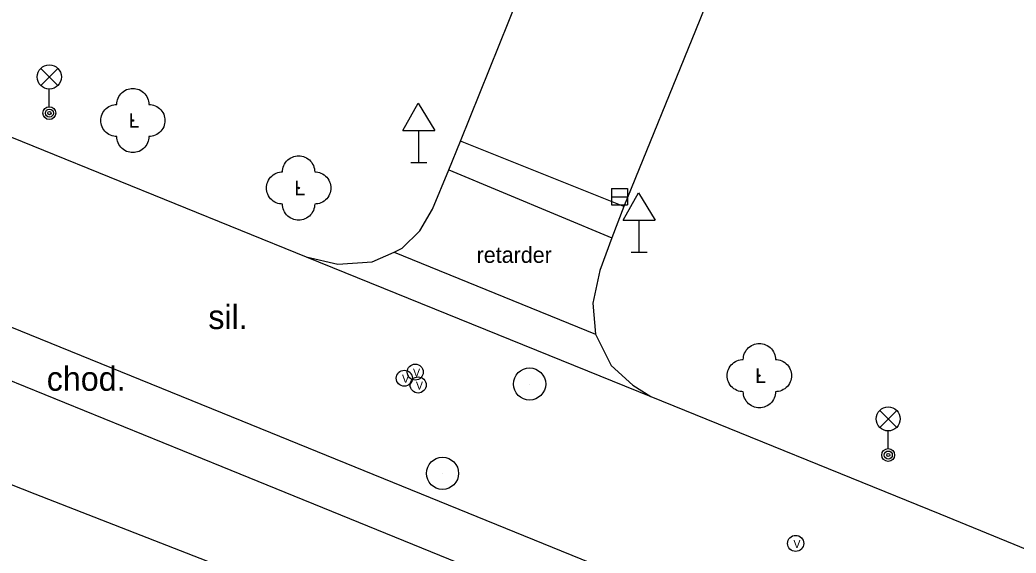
# Model space of a CAD drawing. Extents: x -836568 to -836015, y -1070547 to -1070212.
# Drawn here: x -836360.58 to -836329.58, y -1070416.28 to -1070399.69 of the extents above; entities that cross this region are included whole.
import ezdxf

# ---------------------------------------------------------------- set-up
doc = ezdxf.new("R2010")
doc.units = 0
for name, color, linetype in [('BodPole_mer', 7, 'Continuous'), ('Doprava_body', 7, 'Continuous'), ('Doprava_hranice', 7, 'Continuous'), ('Doprava_kody', 7, 'Continuous'), ('Doprava_popis', 7, 'Continuous'), ('PovrZnIS_body', 7, 'Continuous'), ('Zelen_body', 7, 'Continuous')]:
    doc.layers.add(name, color=color, linetype=linetype)

msp = doc.modelspace()

# ---------------------------------------------------------------- linework, layer by layer
at = {"layer": 'BodPole_mer'}
for p, q in [((-836339.56, -1070400.02), (-836339.56, -1070400.02)), ((-836359.67, -1070402.59), (-836359.67, -1070402.59)), ((-836357.07, -1070402.82), (-836357.07, -1070402.82)), ((-836346.87, -1070403.46), (-836346.87, -1070403.46)), ((-836348.17, -1070404.13), (-836348.17, -1070404.13)), ((-836347.24, -1070404.36), (-836347.24, -1070404.36)), ((-836351.91, -1070404.92), (-836351.91, -1070404.92)), ((-836341.92, -1070405.19), (-836341.92, -1070405.19)), ((-836347.74, -1070405.58), (-836347.74, -1070405.58)), ((-836341.79, -1070405.5), (-836341.79, -1070405.5)), ((-836348.14, -1070406.25), (-836348.14, -1070406.25)), ((-836342.16, -1070406.47), (-836342.16, -1070406.47)), ((-836348.69, -1070406.79), (-836348.69, -1070406.79)), ((-836351.68, -1070407.06), (-836351.68, -1070407.06)), ((-836348.94, -1070406.92), (-836348.94, -1070406.92)), ((-836341.31, -1070406.92), (-836341.31, -1070406.92)), ((-836350.69, -1070407.29), (-836350.69, -1070407.29)), ((-836349.62, -1070407.22), (-836349.62, -1070407.22)), ((-836342.54, -1070407.49), (-836342.54, -1070407.49)), ((-836342.75, -1070408.5), (-836342.75, -1070408.5)), ((-836342.67, -1070409.47), (-836342.67, -1070409.47)), ((-836342.18, -1070410.44), (-836342.18, -1070410.44)), ((-836348.62, -1070410.84), (-836348.62, -1070410.84)), ((-836348.28, -1070410.65), (-836348.28, -1070410.65)), ((-836337.57, -1070410.76), (-836337.57, -1070410.76)), ((-836348.19, -1070411.05), (-836348.19, -1070411.05)), ((-836344.72, -1070411.02), (-836344.72, -1070411.02)), ((-836341.51, -1070411.06), (-836341.51, -1070411.06)), ((-836340.95, -1070411.41), (-836340.95, -1070411.41)), ((-836353.67, -1070412.18), (-836353.67, -1070412.18)), ((-836333.56, -1070413.23), (-836333.56, -1070413.23)), ((-836354.29, -1070413.6), (-836354.29, -1070413.6)), ((-836347.43, -1070413.8), (-836347.43, -1070413.8)), ((-836360.12, -1070414.44), (-836360.12, -1070414.44)), ((-836331.95, -1070415.06), (-836331.95, -1070415.06)), ((-836336.44, -1070415.98), (-836336.44, -1070415.98))]:
    msp.add_line(p, q, dxfattribs=at)
at = {"layer": 'Doprava_body'}
for p, q in [((-836348.67, -1070403.13), (-836348.189, -1070402.276)), ((-836348.189, -1070402.276), (-836347.67, -1070403.13)), ((-836348.67, -1070403.13), (-836347.67, -1070403.13)), ((-836348.17, -1070404.13), (-836348.17, -1070403.13)), ((-836348.42, -1070404.13), (-836347.92, -1070404.13)), ((-836341.81, -1070405.92), (-836341.329, -1070405.066)), ((-836341.329, -1070405.066), (-836340.81, -1070405.92)), ((-836341.81, -1070405.92), (-836340.81, -1070405.92)), ((-836341.31, -1070406.92), (-836341.31, -1070405.92)), ((-836341.56, -1070406.92), (-836341.06, -1070406.92))]:
    msp.add_line(p, q, dxfattribs=at)
at = {"layer": 'Doprava_hranice'}
for p, q in [((-836341.79, -1070405.5), (-836346.87, -1070403.46)), ((-836347.24, -1070404.36), (-836342.16, -1070406.47)), ((-836348.94, -1070406.92), (-836342.67, -1070409.47))]:
    msp.add_line(p, q, dxfattribs=at)
for points in [[(-836331.66, -1070380.54), (-836339.56, -1070400.02), (-836341.79, -1070405.5), (-836342.16, -1070406.47), (-836342.54, -1070407.49), (-836342.75, -1070408.5), (-836342.67, -1070409.47), (-836342.18, -1070410.44), (-836341.51, -1070411.06), (-836340.95, -1070411.41)], [(-836354.29, -1070413.6), (-836369.6, -1070407.37), (-836381.91, -1070402.37), (-836385.59, -1070400.85), (-836388.36, -1070399.67), (-836391.13, -1070398.46), (-836393.85, -1070397.22), (-836395.73, -1070396.35), (-836398.41, -1070395.08), (-836401.16, -1070393.77), (-836403.85, -1070392.4), (-836406.54, -1070391.05), (-836409.24, -1070389.65), (-836411.89, -1070388.24), (-836414.55, -1070386.78), (-836417.54, -1070385.1), (-836418.59, -1070387.07)], [(-836396.93, -1070387.99), (-836395.12, -1070388.87), (-836392.38, -1070390.14), (-836389.65, -1070391.39), (-836386.89, -1070392.61), (-836384.17, -1070393.78), (-836382.29, -1070394.58), (-836379.84, -1070395.6), (-836379.24, -1070395.86), (-836376.76, -1070396.89), (-836369.55, -1070399.81), (-836361.91, -1070402.91), (-836351.68, -1070407.06)], [(-836294.78, -1070436.14), (-836298.75, -1070434.54), (-836300.99, -1070433.61), (-836301.95, -1070433.21), (-836302.68, -1070432.9), (-836308.94, -1070430.38), (-836313.57, -1070428.51), (-836318.21, -1070426.63), (-836324.7, -1070423.98), (-836329.32, -1070422.08), (-836333.96, -1070420.19), (-836342.84, -1070416.58), (-836353.67, -1070412.18), (-836369.06, -1070405.92), (-836381.28, -1070400.95), (-836385.01, -1070399.41), (-836387.75, -1070398.25), (-836390.49, -1070397.04), (-836393.21, -1070395.81), (-836395.03, -1070394.97), (-836397.75, -1070393.68), (-836399.24, -1070392.97)], [(-836351.68, -1070407.06), (-836350.69, -1070407.29), (-836349.62, -1070407.22), (-836348.94, -1070406.92), (-836348.69, -1070406.79), (-836348.14, -1070406.25), (-836347.74, -1070405.58), (-836347.24, -1070404.36), (-836346.87, -1070403.46), (-836345.07, -1070398.97)], [(-836351.68, -1070407.06), (-836340.95, -1070411.41), (-836331.95, -1070415.06), (-836322.39, -1070418.98), (-836311.25, -1070423.49), (-836299.94, -1070428.08), (-836299, -1070428.44), (-836298.27, -1070428.74)], [(-836370.7, -1070410.27), (-836360.12, -1070414.44), (-836352.3, -1070417.49), (-836345.8, -1070420.64)], [(-836282.83, -1070440.54), (-836283.39, -1070441.99), (-836288.97, -1070439.98), (-836292.82, -1070438.51), (-836295.89, -1070437.33), (-836299.06, -1070436.06), (-836309.56, -1070431.79), (-836314.22, -1070429.91), (-836319.37, -1070427.82), (-836325.29, -1070425.39), (-836329.9, -1070423.52), (-836331.04, -1070426.22), (-836335.67, -1070424.36), (-836334.55, -1070421.64), (-836343.54, -1070417.97), (-836354.29, -1070413.6)]]:
    msp.add_lwpolyline(points, dxfattribs=at)
at = {"layer": 'PovrZnIS_body'}
for p, q in [((-836359.935, -1070401.73), (-836359.405, -1070401.2)), ((-836359.935, -1070401.2), (-836359.405, -1070401.73)), ((-836359.67, -1070402.39), (-836359.67, -1070401.84)), ((-836342.17, -1070404.94), (-836341.67, -1070404.94)), ((-836342.17, -1070404.94), (-836342.17, -1070405.44)), ((-836341.67, -1070404.94), (-836341.67, -1070405.44)), ((-836342.17, -1070405.19), (-836341.67, -1070405.19)), ((-836342.17, -1070405.44), (-836341.67, -1070405.44)), ((-836333.825, -1070412.37), (-836333.295, -1070411.84)), ((-836333.825, -1070411.84), (-836333.295, -1070412.37)), ((-836333.56, -1070413.03), (-836333.56, -1070412.48))]:
    msp.add_line(p, q, dxfattribs=at)
for centre, radius in [((-836348.28, -1070410.65), 0.25), ((-836344.72, -1070411.02), 0.5), ((-836348.62, -1070410.84), 0.25), ((-836348.19, -1070411.05), 0.25), ((-836347.43, -1070413.8), 0.5), ((-836336.44, -1070415.98), 0.25)]:
    msp.add_circle(centre, radius, dxfattribs=at)
for centre, major_axis in [((-836359.67, -1070401.465), (0.375, 0)), ((-836359.67, -1070402.59), (0.2, 0)), ((-836359.666, -1070402.59), (0.125, 0)), ((-836359.666, -1070402.59), (0.05, 0)), ((-836333.56, -1070412.105), (0.375, 0)), ((-836333.56, -1070413.23), (0.2, 0)), ((-836333.556, -1070413.23), (0.125, 0)), ((-836333.556, -1070413.23), (0.05, 0))]:
    msp.add_ellipse(centre, major_axis=major_axis, ratio=0.999998, dxfattribs=at)
at = {"layer": 'Zelen_body'}
for p, q in [((-836357.07, -1070402.82), (-836357.07, -1070402.82)), ((-836351.91, -1070404.92), (-836351.91, -1070404.92)), ((-836337.57, -1070410.76), (-836337.57, -1070410.76))]:
    msp.add_line(p, q, dxfattribs=at)
for points in [[(-836357.57, -1070402.32), (-836357.568, -1070402.272), (-836357.56, -1070402.223), (-836357.548, -1070402.173), (-836357.53, -1070402.124), (-836357.506, -1070402.075), (-836357.477, -1070402.029), (-836357.443, -1070401.986), (-836357.404, -1070401.947), (-836357.361, -1070401.913), (-836357.315, -1070401.884), (-836357.266, -1070401.86), (-836357.217, -1070401.842), (-836357.167, -1070401.83), (-836357.118, -1070401.822), (-836357.07, -1070401.82), (-836357.022, -1070401.822), (-836356.973, -1070401.83), (-836356.923, -1070401.842), (-836356.874, -1070401.86), (-836356.825, -1070401.884), (-836356.779, -1070401.913), (-836356.736, -1070401.947), (-836356.697, -1070401.986), (-836356.663, -1070402.029), (-836356.634, -1070402.075), (-836356.61, -1070402.124), (-836356.592, -1070402.173), (-836356.58, -1070402.223), (-836356.572, -1070402.272), (-836356.57, -1070402.32)], [(-836357.57, -1070403.32), (-836357.618, -1070403.318), (-836357.667, -1070403.31), (-836357.717, -1070403.298), (-836357.766, -1070403.28), (-836357.815, -1070403.256), (-836357.861, -1070403.227), (-836357.904, -1070403.193), (-836357.943, -1070403.154), (-836357.977, -1070403.111), (-836358.006, -1070403.065), (-836358.03, -1070403.016), (-836358.048, -1070402.967), (-836358.06, -1070402.917), (-836358.068, -1070402.868), (-836358.07, -1070402.82), (-836358.068, -1070402.772), (-836358.06, -1070402.723), (-836358.048, -1070402.673), (-836358.03, -1070402.624), (-836358.006, -1070402.575), (-836357.977, -1070402.529), (-836357.943, -1070402.486), (-836357.904, -1070402.447), (-836357.861, -1070402.413), (-836357.815, -1070402.384), (-836357.766, -1070402.36), (-836357.717, -1070402.342), (-836357.667, -1070402.33), (-836357.618, -1070402.322), (-836357.57, -1070402.32)], [(-836356.57, -1070402.32), (-836356.522, -1070402.322), (-836356.473, -1070402.33), (-836356.423, -1070402.342), (-836356.374, -1070402.36), (-836356.325, -1070402.384), (-836356.279, -1070402.413), (-836356.236, -1070402.447), (-836356.197, -1070402.486), (-836356.163, -1070402.529), (-836356.134, -1070402.575), (-836356.11, -1070402.624), (-836356.092, -1070402.673), (-836356.08, -1070402.723), (-836356.072, -1070402.772), (-836356.07, -1070402.82), (-836356.072, -1070402.868), (-836356.08, -1070402.917), (-836356.092, -1070402.967), (-836356.11, -1070403.016), (-836356.134, -1070403.065), (-836356.163, -1070403.111), (-836356.197, -1070403.154), (-836356.236, -1070403.193), (-836356.279, -1070403.227), (-836356.325, -1070403.256), (-836356.374, -1070403.28), (-836356.423, -1070403.298), (-836356.473, -1070403.31), (-836356.522, -1070403.318), (-836356.57, -1070403.32)], [(-836356.57, -1070403.32), (-836356.572, -1070403.368), (-836356.58, -1070403.417), (-836356.592, -1070403.467), (-836356.61, -1070403.516), (-836356.634, -1070403.565), (-836356.663, -1070403.611), (-836356.697, -1070403.654), (-836356.736, -1070403.693), (-836356.779, -1070403.727), (-836356.825, -1070403.756), (-836356.874, -1070403.78), (-836356.923, -1070403.798), (-836356.973, -1070403.81), (-836357.022, -1070403.818), (-836357.07, -1070403.82), (-836357.118, -1070403.818), (-836357.167, -1070403.81), (-836357.217, -1070403.798), (-836357.266, -1070403.78), (-836357.315, -1070403.756), (-836357.361, -1070403.727), (-836357.404, -1070403.693), (-836357.443, -1070403.654), (-836357.477, -1070403.611), (-836357.506, -1070403.565), (-836357.53, -1070403.516), (-836357.548, -1070403.467), (-836357.56, -1070403.417), (-836357.568, -1070403.368), (-836357.57, -1070403.32)], [(-836352.41, -1070404.42), (-836352.408, -1070404.372), (-836352.4, -1070404.323), (-836352.388, -1070404.273), (-836352.37, -1070404.224), (-836352.346, -1070404.175), (-836352.317, -1070404.129), (-836352.283, -1070404.086), (-836352.244, -1070404.047), (-836352.201, -1070404.013), (-836352.155, -1070403.984), (-836352.106, -1070403.96), (-836352.057, -1070403.942), (-836352.007, -1070403.93), (-836351.958, -1070403.922), (-836351.91, -1070403.92), (-836351.862, -1070403.922), (-836351.813, -1070403.93), (-836351.763, -1070403.942), (-836351.714, -1070403.96), (-836351.665, -1070403.984), (-836351.619, -1070404.013), (-836351.576, -1070404.047), (-836351.537, -1070404.086), (-836351.503, -1070404.129), (-836351.474, -1070404.175), (-836351.45, -1070404.224), (-836351.432, -1070404.273), (-836351.42, -1070404.323), (-836351.412, -1070404.372), (-836351.41, -1070404.42)], [(-836352.41, -1070405.42), (-836352.458, -1070405.418), (-836352.507, -1070405.41), (-836352.557, -1070405.398), (-836352.606, -1070405.38), (-836352.655, -1070405.356), (-836352.701, -1070405.327), (-836352.744, -1070405.293), (-836352.783, -1070405.254), (-836352.817, -1070405.211), (-836352.846, -1070405.165), (-836352.87, -1070405.116), (-836352.888, -1070405.067), (-836352.9, -1070405.017), (-836352.908, -1070404.968), (-836352.91, -1070404.92), (-836352.908, -1070404.872), (-836352.9, -1070404.823), (-836352.888, -1070404.773), (-836352.87, -1070404.724), (-836352.846, -1070404.675), (-836352.817, -1070404.629), (-836352.783, -1070404.586), (-836352.744, -1070404.547), (-836352.701, -1070404.513), (-836352.655, -1070404.484), (-836352.606, -1070404.46), (-836352.557, -1070404.442), (-836352.507, -1070404.43), (-836352.458, -1070404.422), (-836352.41, -1070404.42)], [(-836351.41, -1070404.42), (-836351.362, -1070404.422), (-836351.313, -1070404.43), (-836351.263, -1070404.442), (-836351.214, -1070404.46), (-836351.165, -1070404.484), (-836351.119, -1070404.513), (-836351.076, -1070404.547), (-836351.037, -1070404.586), (-836351.003, -1070404.629), (-836350.974, -1070404.675), (-836350.95, -1070404.724), (-836350.932, -1070404.773), (-836350.92, -1070404.823), (-836350.912, -1070404.872), (-836350.91, -1070404.92), (-836350.912, -1070404.968), (-836350.92, -1070405.017), (-836350.932, -1070405.067), (-836350.95, -1070405.116), (-836350.974, -1070405.165), (-836351.003, -1070405.211), (-836351.037, -1070405.254), (-836351.076, -1070405.293), (-836351.119, -1070405.327), (-836351.165, -1070405.356), (-836351.214, -1070405.38), (-836351.263, -1070405.398), (-836351.313, -1070405.41), (-836351.362, -1070405.418), (-836351.41, -1070405.42)], [(-836351.41, -1070405.42), (-836351.412, -1070405.468), (-836351.42, -1070405.517), (-836351.432, -1070405.567), (-836351.45, -1070405.616), (-836351.474, -1070405.665), (-836351.503, -1070405.711), (-836351.537, -1070405.754), (-836351.576, -1070405.793), (-836351.619, -1070405.827), (-836351.665, -1070405.856), (-836351.714, -1070405.88), (-836351.763, -1070405.898), (-836351.813, -1070405.91), (-836351.862, -1070405.918), (-836351.91, -1070405.92), (-836351.958, -1070405.918), (-836352.007, -1070405.91), (-836352.057, -1070405.898), (-836352.106, -1070405.88), (-836352.155, -1070405.856), (-836352.201, -1070405.827), (-836352.244, -1070405.793), (-836352.283, -1070405.754), (-836352.317, -1070405.711), (-836352.346, -1070405.665), (-836352.37, -1070405.616), (-836352.388, -1070405.567), (-836352.4, -1070405.517), (-836352.408, -1070405.468), (-836352.41, -1070405.42)], [(-836338.07, -1070410.26), (-836338.068, -1070410.212), (-836338.06, -1070410.163), (-836338.048, -1070410.113), (-836338.03, -1070410.064), (-836338.006, -1070410.015), (-836337.977, -1070409.969), (-836337.943, -1070409.926), (-836337.904, -1070409.887), (-836337.861, -1070409.853), (-836337.815, -1070409.824), (-836337.766, -1070409.8), (-836337.717, -1070409.782), (-836337.667, -1070409.77), (-836337.618, -1070409.762), (-836337.57, -1070409.76), (-836337.522, -1070409.762), (-836337.473, -1070409.77), (-836337.423, -1070409.782), (-836337.374, -1070409.8), (-836337.325, -1070409.824), (-836337.279, -1070409.853), (-836337.236, -1070409.887), (-836337.197, -1070409.926), (-836337.163, -1070409.969), (-836337.134, -1070410.015), (-836337.11, -1070410.064), (-836337.092, -1070410.113), (-836337.08, -1070410.163), (-836337.072, -1070410.212), (-836337.07, -1070410.26)], [(-836338.07, -1070411.26), (-836338.118, -1070411.258), (-836338.167, -1070411.25), (-836338.217, -1070411.238), (-836338.266, -1070411.22), (-836338.315, -1070411.196), (-836338.361, -1070411.167), (-836338.404, -1070411.133), (-836338.443, -1070411.094), (-836338.477, -1070411.051), (-836338.506, -1070411.005), (-836338.53, -1070410.956), (-836338.548, -1070410.907), (-836338.56, -1070410.857), (-836338.568, -1070410.808), (-836338.57, -1070410.76), (-836338.568, -1070410.712), (-836338.56, -1070410.663), (-836338.548, -1070410.613), (-836338.53, -1070410.564), (-836338.506, -1070410.515), (-836338.477, -1070410.469), (-836338.443, -1070410.426), (-836338.404, -1070410.387), (-836338.361, -1070410.353), (-836338.315, -1070410.324), (-836338.266, -1070410.3), (-836338.217, -1070410.282), (-836338.167, -1070410.27), (-836338.118, -1070410.262), (-836338.07, -1070410.26)], [(-836337.07, -1070410.26), (-836337.022, -1070410.262), (-836336.973, -1070410.27), (-836336.923, -1070410.282), (-836336.874, -1070410.3), (-836336.825, -1070410.324), (-836336.779, -1070410.353), (-836336.736, -1070410.387), (-836336.697, -1070410.426), (-836336.663, -1070410.469), (-836336.634, -1070410.515), (-836336.61, -1070410.564), (-836336.592, -1070410.613), (-836336.58, -1070410.663), (-836336.572, -1070410.712), (-836336.57, -1070410.76), (-836336.572, -1070410.808), (-836336.58, -1070410.857), (-836336.592, -1070410.907), (-836336.61, -1070410.956), (-836336.634, -1070411.005), (-836336.663, -1070411.051), (-836336.697, -1070411.094), (-836336.736, -1070411.133), (-836336.779, -1070411.167), (-836336.825, -1070411.196), (-836336.874, -1070411.22), (-836336.923, -1070411.238), (-836336.973, -1070411.25), (-836337.022, -1070411.258), (-836337.07, -1070411.26)], [(-836337.07, -1070411.26), (-836337.072, -1070411.308), (-836337.08, -1070411.357), (-836337.092, -1070411.407), (-836337.11, -1070411.456), (-836337.134, -1070411.505), (-836337.163, -1070411.551), (-836337.197, -1070411.594), (-836337.236, -1070411.633), (-836337.279, -1070411.667), (-836337.325, -1070411.696), (-836337.374, -1070411.72), (-836337.423, -1070411.738), (-836337.473, -1070411.75), (-836337.522, -1070411.758), (-836337.57, -1070411.76), (-836337.618, -1070411.758), (-836337.667, -1070411.75), (-836337.717, -1070411.738), (-836337.766, -1070411.72), (-836337.815, -1070411.696), (-836337.861, -1070411.667), (-836337.904, -1070411.633), (-836337.943, -1070411.594), (-836337.977, -1070411.551), (-836338.006, -1070411.505), (-836338.03, -1070411.456), (-836338.048, -1070411.407), (-836338.06, -1070411.357), (-836338.068, -1070411.308), (-836338.07, -1070411.26)]]:
    msp.add_lwpolyline(points, dxfattribs=at)
for centre in [(-836357.07, -1070402.82), (-836351.91, -1070404.92), (-836337.57, -1070410.76)]:
    msp.add_ellipse(centre, major_axis=(0.025, 0), ratio=0.999997, dxfattribs=at)

# ---------------------------------------------------------------- texts
at = {"layer": 'Doprava_kody'}
for s, p in [('sil.', (-836354.72, -1070409.31)), ('chod.', (-836359.75, -1070411.23))]:
    msp.add_text(s, height=0.75, dxfattribs=at).set_placement(p)
at = {"layer": 'Doprava_popis'}
msp.add_text('retarder', height=0.5, dxfattribs=at).set_placement((-836346.37, -1070407.25))
at = {"layer": 'PovrZnIS_body'}
for p in [(-836348.351, -1070410.793), (-836348.691, -1070410.983), (-836348.261, -1070411.193), (-836336.511, -1070416.123)]:
    msp.add_text('V', height=0.25, dxfattribs=at).set_placement(p)
at = {"layer": 'Zelen_body'}
for p in [(-836357.201, -1070403.045), (-836352.041, -1070405.145), (-836337.701, -1070410.985)]:
    msp.add_text('L', height=0.45, dxfattribs=at).set_placement(p)

doc.saveas('drawing.dxf')
